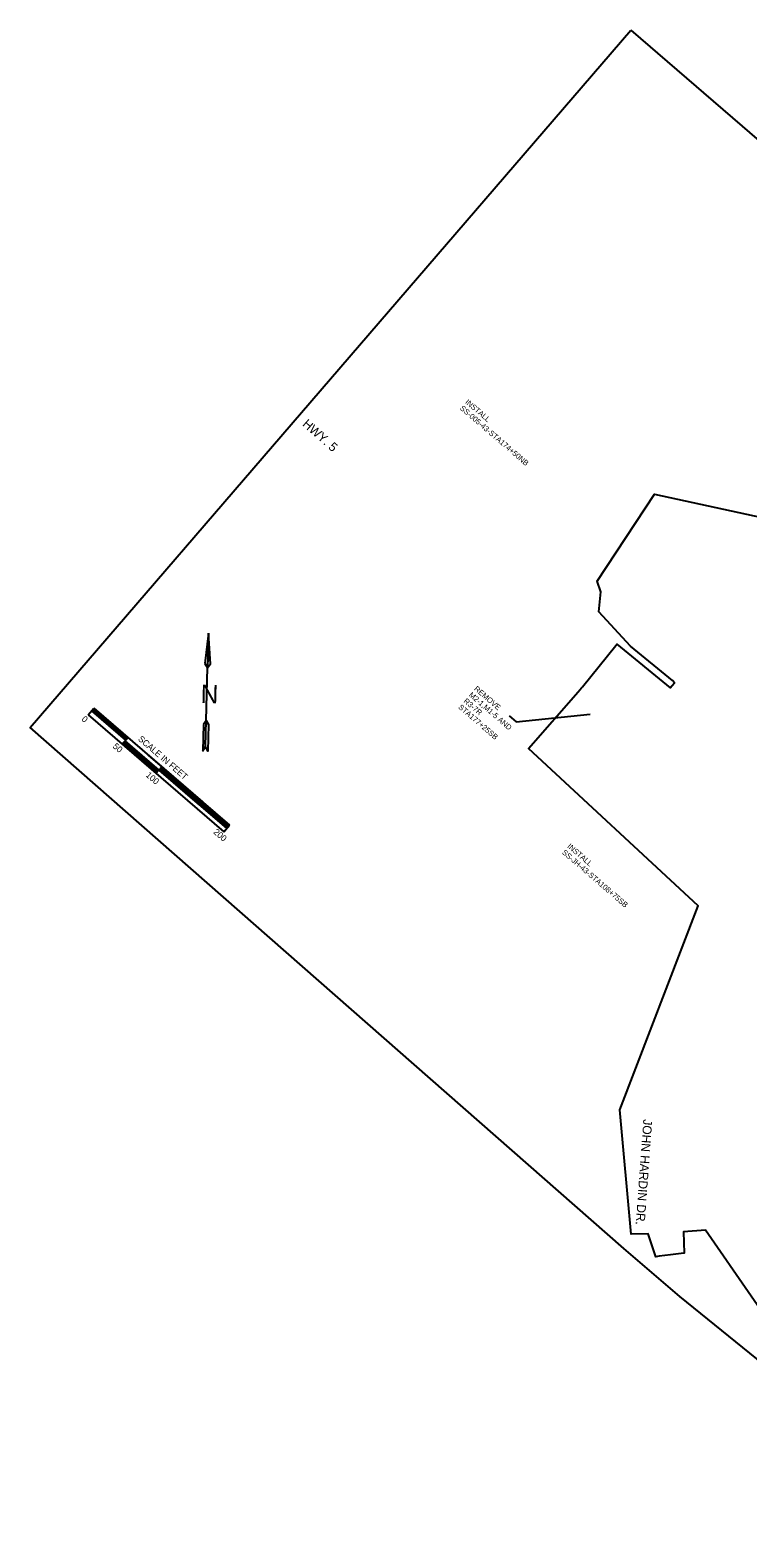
# Model space of a CAD drawing. Extents: x 1289840 to 1295361, y 220865 to 226414.
# Drawn here: x 1291398 to 1292199, y 223919 to 225602 of the extents above; entities that cross this region are included whole.
import ezdxf

# ---------------------------------------------------------------- set-up
doc = ezdxf.new("R2010")
doc.units = 0
for name, color, linetype in [('level 1050', 7, 'Continuous'), ('Plan Text', 7, 'Continuous'), ('R_No Plot', 7, 'Continuous'), ('SIGN CALLOUTS', 7, 'Continuous'), ('SIGN STRUC', 7, 'Continuous')]:
    doc.layers.add(name, color=color, linetype=linetype)

msp = doc.modelspace()

# ---------------------------------------------------------------- linework, layer by layer
at = {"layer": 'level 1050'}
for p, q in [((1291932.5, 224836.9), (1291940.3, 224830.1)), ((1291940.3, 224830.1), (1292023, 224838.6))]:
    msp.add_line(p, q, dxfattribs=at)
at = {"layer": 'Plan Text'}
for p, q in [((1291596.9, 224929), (1291592.8, 224895.1)), ((1291592.8, 224895.1), (1291595.9, 224890.5)), ((1291594.3, 224831.7), (1291595.9, 224890.6))]:
    msp.add_line(p, q, dxfattribs=at)
for points in [[(1291596.9, 224928.9), (1291595.9, 224890.5), (1291599.1, 224894.9)], [(1291591.3, 224827.1), (1291590.5, 224797.7), (1291593.5, 224802.4), (1291594.3, 224831.7)], [(1291594.3, 224831.7), (1291597, 224827), (1291596.3, 224797.5), (1291593.5, 224802.4)]]:
    msp.add_lwpolyline(points, close=True, dxfattribs=at)
at = {"layer": 'R_No Plot'}
msp.add_lwpolyline([(1292068.4, 225602), (1292922.4, 224865.9), (1292940.8, 224572.7), (1292894.8, 224434), (1292959.1, 224279.4), (1292757.6, 224052.5), (1292731.5, 224041), (1292674.8, 224003.2), (1292664, 223944.5), (1292641.2, 223919.4), (1292304.8, 224042), (1292123.2, 224188.6), (1292060.7, 224242.5), (1291397.7, 224823.8)], close=True, dxfattribs=at)
msp.add_lwpolyline([(1292304.8, 224042), (1292151.7, 224262.8), (1292127.3, 224261.1), (1292128, 224237.2), (1292124.5, 224236.7), (1292112.8, 224235.3), (1292100, 224233.7), (1292096.3, 224233.2), (1292087.7, 224258.8), (1292068.6, 224258.3), (1292056, 224397.1), (1292143.5, 224624.9), (1291954.1, 224800.3), (1292009.7, 224863.6), (1292013.4, 224868.1), (1292014.3, 224869.3), (1292051.6, 224915.1), (1292052.9, 224916.9), (1292112.1, 224868), (1292114.6, 224870.5), (1292117.2, 224873.7), (1292115, 224876.1), (1292068, 224914.4), (1292032.7, 224953), (1292035, 224975), (1292030.8, 224987.1), (1292094.8, 225084), (1292317.3, 225035.9)], dxfattribs=at)
at = {"layer": 'SIGN CALLOUTS'}
for p, q in [((1291462.5, 224837.9), (1291468.8, 224845.2)), ((1291462.5, 224837.9), (1291614.1, 224707.4)), ((1291466.2, 224842.2), (1291504.1, 224809.5)), ((1291466.7, 224842.8), (1291504.6, 224810.1)), ((1291467.2, 224843.4), (1291505.1, 224810.7)), ((1291467.7, 224844), (1291505.6, 224811.3)), ((1291468.3, 224844.6), (1291506.2, 224811.9)), ((1291468.8, 224845.2), (1291590, 224740.8)), ((1291468.8, 224845.2), (1291499.1, 224819.1)), ((1291492.8, 224811.8), (1291523.1, 224785.7)), ((1291500.4, 224805.3), (1291506.7, 224812.5)), ((1291500.9, 224805.9), (1291538.8, 224773.2)), ((1291501.5, 224806.5), (1291539.3, 224773.9)), ((1291502, 224807.1), (1291539.9, 224774.5)), ((1291502.5, 224807.7), (1291540.4, 224775.1)), ((1291503, 224808.3), (1291540.9, 224775.7)), ((1291503.5, 224808.9), (1291541.4, 224776.3)), ((1291529.4, 224793), (1291620.3, 224714.6)), ((1291538.3, 224772.6), (1291544.6, 224779.9)), ((1291541.4, 224776.3), (1291586.9, 224737.1)), ((1291541.4, 224776.3), (1291617.2, 224711)), ((1291541.9, 224776.9), (1291617.7, 224711.6)), ((1291542.5, 224777.5), (1291618.2, 224712.2)), ((1291543, 224778.1), (1291618.8, 224712.8)), ((1291543.5, 224778.7), (1291619.3, 224713.4)), ((1291544, 224779.3), (1291619.8, 224714)), ((1291614, 224707.4), (1291620.3, 224714.6))]:
    msp.add_line(p, q, dxfattribs=at)

# ---------------------------------------------------------------- texts
at = {"layer": 'level 1050'}
for s, p in [('INSTALL', (1291882.9, 225186.1)), ('SS-005-43-STA174+50NB', (1291877, 225179.2)), ('REMOVE', (1291892.8, 224866.1)), ('R3-7R', (1291881.1, 224852.4)), ('M2-1,M1-5 AND', (1291887, 224859.3)), ('STA177+25SB', (1291875.2, 224845.6)), ('SS-JH-43-STA108+75SB', (1291991, 224683.5)), ('INSTALL', (1291996.9, 224690.3))]:
    msp.add_text(s, height=6, rotation=319.2179, dxfattribs=at).set_placement(p)
at = {"layer": 'Plan Text'}
msp.add_text('N', height=20.4, rotation=358.4728, dxfattribs=at).set_placement((1291587.9, 224851.1))
at = {"layer": 'SIGN CALLOUTS'}
for s, height, p in [('0', 7, (1291454.5, 224832.1)), ('50', 7, (1291489.4, 224801.8)), ('SCALE IN FEET', 7.001, (1291517.6, 224810)), ('100', 7, (1291526.2, 224769.7)), ('200', 7, (1291601.7, 224706.1))]:
    msp.add_text(s, height=height, rotation=319.2566, dxfattribs=at).set_placement(p)
at = {"layer": 'SIGN STRUC'}
for s, rotation, p in [('HWY. 5', 318.4636, (1291701, 225161.2)), ('JOHN HARDIN DR.', 265.8048, (1292082.4, 224386.8))]:
    msp.add_text(s, height=10, rotation=rotation, dxfattribs=at).set_placement(p)

doc.saveas('drawing.dxf')
